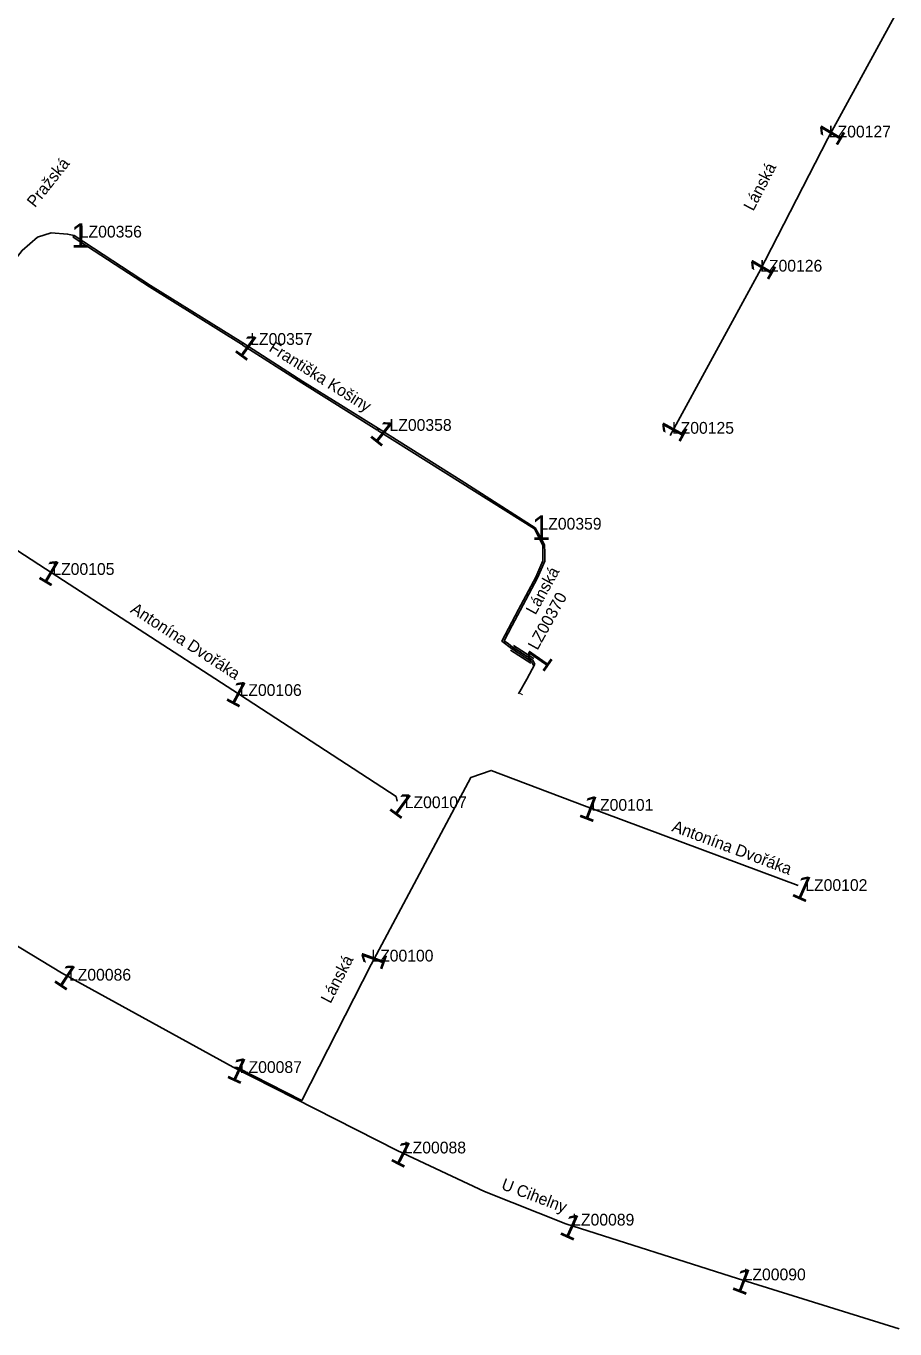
# Model space of a CAD drawing. Extents: x -736540 to -735418, y -1033000 to -1031598.
# Drawn here: x -736131.8 to -735947.1, y -1032931.9 to -1032655 of the extents above; entities that cross this region are included whole.
import ezdxf

# ---------------------------------------------------------------- set-up
doc = ezdxf.new("R2010")
doc.units = 0
for name, color, linetype in [('ftf_2010', 7, 'Continuous'), ('ftf_2100', 7, 'Continuous'), ('ftf_2140', 7, 'Continuous'), ('ftf_2210', 7, 'Continuous'), ('ftf_3010', 7, 'Continuous'), ('ftf_3010_ftf_3010_gtda_3015_gtda_3015_1', 7, 'Continuous'), ('ftf_3210', 7, 'Continuous'), ('ftf_nu', 7, 'Continuous')]:
    doc.layers.add(name, color=color, linetype=linetype)

msp = doc.modelspace()

# ---------------------------------------------------------------- linework, layer by layer
at = {"layer": 'ftf_2010'}
for points in [[(-735947.19, -1032652.98), (-735961.39, -1032678.94)], [(-735961.39, -1032678.94), (-735976.05, -1032707.51)], [(-736121.53, -1032699.55), (-736122.95, -1032699.23), (-736126.42, -1032698.96), (-736129.3, -1032699.91), (-736132.59, -1032702.72), (-736146.91, -1032720.92)], [(-736121.53, -1032699.55), (-736105.28, -1032710.15), (-736085.71, -1032722.36)], [(-735994.86, -1032742.02), (-735976.05, -1032707.51)], [(-736056.89, -1032740.56), (-736064.93, -1032735.55), (-736072.96, -1032730.54), (-736085.71, -1032722.36)], [(-736023.6, -1032761.64), (-736039.31, -1032751.63), (-736056.89, -1032740.56)], [(-736127.61, -1032770.37), (-736163.8, -1032746.89), (-736167.34, -1032747.62)], [(-736023.6, -1032761.64), (-736022.58, -1032763.45), (-736021.57, -1032765.25), (-736021.54, -1032767), (-736021.51, -1032768.75), (-736022.3, -1032770.54), (-736023.08, -1032772.32), (-736024.91, -1032775.78), (-736026.74, -1032779.23), (-736028.44, -1032782.44), (-736030.13, -1032785.65), (-736029.26, -1032786.32), (-736028.39, -1032786.99), (-736026.23, -1032788.39), (-736024.07, -1032789.78), (-736023.85, -1032790.2), (-736023.64, -1032790.62)], [(-736087.84, -1032796.17), (-736127.61, -1032770.37)], [(-736052.9, -1032819.73), (-736053.14, -1032818.79), (-736087.84, -1032796.17)], [(-736013.08, -1032820.73), (-736032.92, -1032813.21), (-736037.22, -1032814.71), (-736058.45, -1032854.48)], [(-735967.72, -1032837.65), (-736013.08, -1032820.73)], [(-736124.23, -1032856.21), (-736158.51, -1032835.5)], [(-736087.78, -1032876.29), (-736124.23, -1032856.21)], [(-736087.78, -1032876.29), (-736086.92, -1032876.31), (-736073.17, -1032883.33), (-736058.45, -1032854.48)], [(-736052.87, -1032894.01), (-736087.78, -1032876.29)], [(-736017.04, -1032909.56), (-736034.36, -1032902.68), (-736052.87, -1032894.01)], [(-736017.04, -1032909.56), (-735980.57, -1032921.21)], [(-735946.21, -1032931.9), (-735980.57, -1032921.21)]]:
    msp.add_lwpolyline(points, dxfattribs=at)
at = {"layer": 'ftf_2100'}
msp.add_lwpolyline([(-736023.64, -1032790.62), (-736025.37, -1032793.79), (-736027.1, -1032796.96)], dxfattribs=at)
at = {"layer": 'ftf_2140'}
for points in [[(-736121.53, -1032699.55), (-736121.75, -1032699.89), (-736105.5, -1032710.49), (-736085.98, -1032722.66), (-736085.71, -1032722.36), (-736085.83, -1032722.76), (-736073.17, -1032730.88), (-736057.19, -1032740.85), (-736056.89, -1032740.56), (-736057.03, -1032740.95), (-736039.52, -1032751.97), (-736023.69, -1032761.9), (-736023.6, -1032761.64)], [(-736023.64, -1032790.62), (-736024, -1032790.8), (-736024.38, -1032790.06), (-736028.62, -1032787.32), (-736030.64, -1032785.76), (-736027.09, -1032779.04), (-736023.44, -1032772.15), (-736021.91, -1032768.67), (-736021.97, -1032765.36), (-736023.69, -1032761.9)]]:
    msp.add_lwpolyline(points, dxfattribs=at)
at = {"layer": 'ftf_3210'}
for p, q in [((-736023.85, -1032789.44), (-736028.17, -1032786.65)), ((-736024.5, -1032790.45), (-736028.82, -1032787.66))]:
    msp.add_line(p, q, dxfattribs=at)
for points in [[(-736024.07, -1032789.78), (-736024.61, -1032789.43), (-736025.15, -1032789.08), (-736025.42, -1032788.91), (-736025.69, -1032788.73), (-736025.96, -1032788.56), (-736026.23, -1032788.39), (-736026.5, -1032788.21), (-736026.77, -1032788.04), (-736027.04, -1032787.86), (-736027.31, -1032787.69), (-736027.58, -1032787.51), (-736027.85, -1032787.34), (-736028.12, -1032787.16), (-736028.39, -1032786.99)], [(-736024.07, -1032789.78), (-736025.15, -1032789.08), (-736026.23, -1032788.39), (-736027.31, -1032787.69), (-736028.39, -1032786.99)]]:
    msp.add_lwpolyline(points, dxfattribs=at)

# ---------------------------------------------------------------- texts
at = {"layer": 'ftf_2210'}
msp.add_text('-', height=2, rotation=154.1462, dxfattribs=at).set_placement((-736025.76, -1032796.5))
at = {"layer": 'ftf_3010'}
for rotation, p in [(59.1841, (-735959.49, -1032680.82)), (59.592, (-735974.13, -1032709.38)), (323.7365, (-736087.77, -1032724.07)), (321.2544, (-736059.02, -1032742.18)), (61.3943, (-735992.89, -1032743.83)), (329.3624, (-736129.5, -1032772.28)), (55.2066, (-736021.87, -1032792.64)), (331.8826, (-736089.64, -1032798.16)), (323.6455, (-736054.96, -1032821.44)), (339.1572, (-736014.61, -1032822.93)), (336.1171, (-735969.36, -1032839.77)), (70.2215, (-736056.22, -1032855.97)), (326.5406, (-736126.2, -1032858.02)), (335.4521, (-736089.45, -1032878.38)), (333.0089, (-736054.63, -1032896.04)), (335.7622, (-736018.7, -1032911.67)), (339.03, (-735982.1, -1032923.4))]:
    msp.add_text('1', height=5.2, rotation=rotation, dxfattribs=at).set_placement(p)
for p in [(-736122.18, -1032702.15), (-736024.25, -1032764.24)]:
    msp.add_text('1', height=5.2, dxfattribs=at).set_placement(p)
at = {"layer": 'ftf_3010_ftf_3010_gtda_3015_gtda_3015_1'}
for s, p in [('LZ00127', (-735961.17, -1032678.71)), ('LZ00356', (-736120.34, -1032699.98)), ('LZ00126', (-735975.76, -1032707.22)), ('LZ00357', (-736084.12, -1032722.79)), ('LZ00358', (-736054.52, -1032741.06)), ('LZ00125', (-735994.52, -1032741.67)), ('LZ00359', (-736022.66, -1032762.05)), ('LZ00105', (-736126.17, -1032771.67)), ('LZ00106', (-736086.38, -1032797.39)), ('LZ00107', (-736051.29, -1032821.23)), ('LZ00101', (-736011.65, -1032821.79)), ('LZ00102', (-735966.17, -1032838.83)), ('LZ00086', (-736122.64, -1032857.88)), ('LZ00087', (-736086.34, -1032877.5)), ('LZ00088', (-736051.47, -1032894.6)), ('LZ00089', (-736015.7, -1032909.93)), ('LZ00090', (-735979.27, -1032921.57))]:
    msp.add_text(s, height=2.5, dxfattribs=at).set_placement(p)
for s, rotation, p in [('LZ00370', 61.1389, (-736023.09, -1032787.82)), ('LZ00100', 0, (-736058.38, -1032853.82))]:
    msp.add_text(s, height=2.5, rotation=rotation, dxfattribs=at).set_placement(p)
at = {"layer": 'ftf_nu'}
for s, rotation, p in [('Pražská', 51.5585, (-736129.85, -1032693.76)), ('Lánská', 62.6272, (-735977.22, -1032694.51)), ('Františka Košiny', 327.8268, (-736080.34, -1032724)), ('Lánská', 61.2291, (-736023.51, -1032780.31)), ('Antonína Dvořáka', 327.1051, (-736109.77, -1032779.51)), ('Antonína Dvořáka', 339.5067, (-735994.7, -1032826.07)), ('Lánská', 62.7435, (-736067.06, -1032862.89)), ('U Cihelny', 339.213, (-736030.95, -1032902.14))]:
    msp.add_text(s, height=2.5, rotation=rotation, dxfattribs=at).set_placement(p)

doc.saveas('drawing.dxf')
